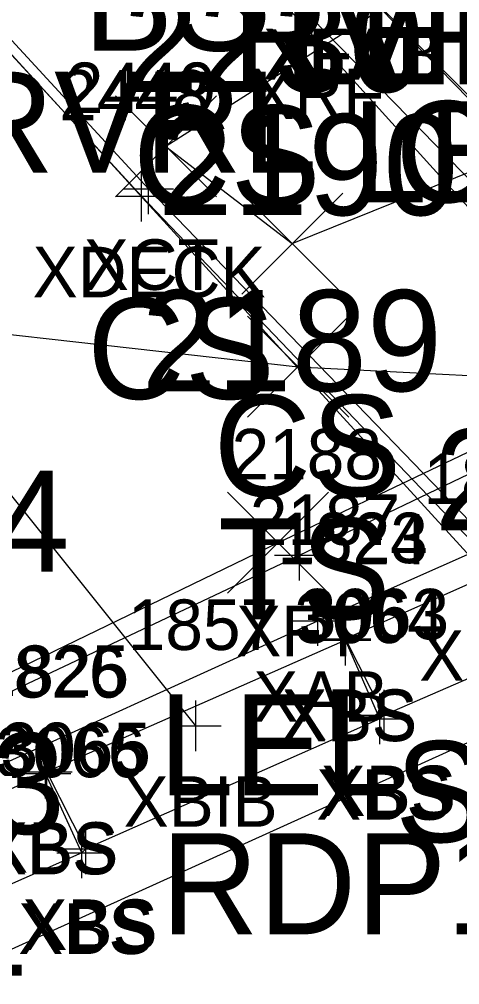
# Model space of a CAD drawing. Extents: x 1504228 to 1506103, y 437717 to 440106.
# Drawn here: x 1505265.52 to 1505274.23, y 438158.68 to 438177.79 of the extents above; entities that cross this region are included whole.
import ezdxf

# ---------------------------------------------------------------- set-up
doc = ezdxf.new("R2010")
doc.units = 0
for name, color, linetype in [('B_A', 7, 'Continuous'), ('B_I', 7, 'Continuous'), ('B_TIC', 7, 'Continuous'), ('BB', 7, 'Continuous'), ('BDC', 7, 'Continuous'), ('BELB', 7, 'Continuous'), ('BF', 7, 'Continuous'), ('BFT', 7, 'Continuous'), ('BR', 7, 'Continuous'), ('BSE', 7, 'Continuous'), ('BSUBM', 7, 'Continuous'), ('L_A', 7, 'Continuous'), ('L_I', 7, 'Continuous'), ('L_TIC', 7, 'Continuous'), ('LARO', 7, 'Continuous'), ('LELB', 7, 'Continuous'), ('P_I', 7, 'Continuous'), ('PET', 7, 'Continuous'), ('R_A', 7, 'Continuous'), ('R_I', 7, 'Continuous')]:
    doc.layers.add(name, color=color, linetype=linetype)

msp = doc.modelspace()

# ---------------------------------------------------------------- linework, layer by layer
at = {"layer": 'B_TIC'}
for p, q in [((1505268.074, 438174.436), (1505268.15, 438174.436)), ((1505267.942, 438174.29), (1505268.017, 438174.29)), ((1505271.067, 438167.183), (1505271.143, 438167.183)), ((1505271.429, 438165.886), (1505271.504, 438165.886)), ((1505271.974, 438165.5), (1505272.049, 438165.5)), ((1505271.977, 438165.525), (1505272.052, 438165.525)), ((1505272.655, 438163.944), (1505272.731, 438163.944)), ((1505272.741, 438164.016), (1505272.817, 438164.016)), ((1505269.013, 438163.806), (1505269.089, 438163.806)), ((1505266.041, 438162.863), (1505266.116, 438162.863)), ((1505266.064, 438162.896), (1505266.14, 438162.896)), ((1505266.76, 438161.287), (1505266.836, 438161.287)), ((1505266.84, 438161.367), (1505266.916, 438161.367))]:
    msp.add_line(p, q, dxfattribs=at)
for points in [[(1505271.307, 438177.317), (1505271.307, 438178.317)], [(1505267.938, 438173.79), (1505267.938, 438174.79)], [(1505268.071, 438173.936), (1505268.071, 438174.936)], [(1505267.571, 438174.436), (1505268.571, 438174.436)], [(1505267.438, 438174.29), (1505268.438, 438174.29)], [(1505271.064, 438166.683), (1505271.064, 438167.683)], [(1505270.564, 438167.183), (1505271.564, 438167.183)], [(1505271.425, 438165.386), (1505271.425, 438166.386)], [(1505271.97, 438165), (1505271.97, 438166)], [(1505271.973, 438165.025), (1505271.973, 438166.025)], [(1505270.925, 438165.886), (1505271.925, 438165.886)], [(1505271.47, 438165.5), (1505272.47, 438165.5)], [(1505271.473, 438165.525), (1505272.473, 438165.525)], [(1505272.738, 438163.516), (1505272.738, 438164.516)], [(1505269.01, 438163.306), (1505269.01, 438164.306)], [(1505272.652, 438163.444), (1505272.652, 438164.444)], [(1505272.152, 438163.944), (1505273.152, 438163.944)], [(1505272.238, 438164.016), (1505273.238, 438164.016)], [(1505268.51, 438163.806), (1505269.51, 438163.806)], [(1505266.037, 438162.363), (1505266.037, 438163.363)], [(1505266.061, 438162.396), (1505266.061, 438163.396)], [(1505265.537, 438162.863), (1505266.537, 438162.863)], [(1505265.561, 438162.896), (1505266.561, 438162.896)], [(1505266.757, 438160.787), (1505266.757, 438161.787)], [(1505266.837, 438160.867), (1505266.837, 438161.867)], [(1505266.257, 438161.287), (1505267.257, 438161.287)], [(1505266.337, 438161.367), (1505267.337, 438161.367)]]:
    msp.add_lwpolyline(points, dxfattribs=at)
at = {"layer": 'BB'}
for points in [[(1505279.36, 438168.588), (1505247.631, 438203.673)], [(1505274.859, 438166.697), (1505243.111, 438201.465)], [(1505269.01, 438163.806), (1505239.92, 438200.195)]]:
    msp.add_lwpolyline(points, dxfattribs=at)
at = {"layer": 'BDC'}
msp.add_lwpolyline([(1505211.925, 438243.921), (1505227.096, 438222.88), (1505239.823, 438206.409), (1505253.849, 438189.887), (1505268.071, 438174.436), (1505276.686, 438165.513)], dxfattribs=at)
at = {"layer": 'BELB'}
msp.add_lwpolyline([(1505211.812, 438243.704), (1505226.972, 438222.631), (1505239.63, 438206.209), (1505253.732, 438189.745), (1505267.938, 438174.29), (1505276.516, 438165.316)], dxfattribs=at)
at = {"layer": 'BF'}
for points in [[(1505211.925, 438243.921), (1505216.347, 438245.376), (1505218.618, 438242.78), (1505219.411, 438243.379), (1505231.883, 438226.243), (1505244.785, 438210.059), (1505258.149, 438194.034), (1505272.082, 438178.605), (1505279.641, 438170.867), (1505278.911, 438170.024), (1505281.091, 438167.856), (1505276.686, 438165.513)], [(1505219.325, 438243.288), (1505231.877, 438226.273), (1505244.695, 438209.964), (1505258.118, 438194.019), (1505272.126, 438178.595), (1505280.957, 438169.659)]]:
    msp.add_lwpolyline(points, dxfattribs=at)
at = {"layer": 'BFT'}
msp.add_lwpolyline([(1505211.711, 438138.978), (1505211.593, 438140.8), (1505215.376, 438142.417), (1505230.303, 438149.002), (1505243.278, 438154.766), (1505246.019, 438155.885), (1505263.291, 438163.511), (1505271.064, 438167.183), (1505276.649, 438169.866), (1505288.201, 438174.699), (1505288.73, 438173.49)], dxfattribs=at)
at = {"layer": 'BR'}
msp.add_lwpolyline([(1505218.618, 438242.78), (1505231.125, 438225.649), (1505244.017, 438209.29), (1505257.36, 438193.318), (1505271.307, 438177.817), (1505278.911, 438170.024)], dxfattribs=at)
at = {"layer": 'BSE'}
for points in [[(1505280.986, 438169.409), (1505277.349, 438167.858), (1505277.284, 438167.888), (1505271.973, 438165.525), (1505271.97, 438165.5), (1505266.061, 438162.896), (1505266.037, 438162.863), (1505260.289, 438160.295)], [(1505281.759, 438167.888), (1505278.121, 438166.325), (1505278.032, 438166.318), (1505272.738, 438164.016), (1505272.652, 438163.944), (1505266.837, 438161.367), (1505266.757, 438161.287), (1505261.073, 438158.776)], [(1505272.652, 438163.944), (1505271.97, 438165.5)], [(1505272.738, 438164.016), (1505271.973, 438165.525)], [(1505266.757, 438161.287), (1505266.037, 438162.863)], [(1505266.837, 438161.367), (1505266.061, 438162.896)]]:
    msp.add_lwpolyline(points, dxfattribs=at)
at = {"layer": 'BSUBM'}
msp.add_lwpolyline([(1505214.761, 438127.389), (1505213.65, 438134.809), (1505212.657, 438139.975), (1505231.134, 438147.944), (1505243.637, 438153.412), (1505246.753, 438154.837), (1505263.932, 438162.477), (1505271.425, 438165.886), (1505277.465, 438168.561), (1505287.974, 438173.167), (1505291.052, 438171.05), (1505297.268, 438166.649), (1505302.136, 438162.984), (1505307.468, 438159.403), (1505307.306, 438158.962)], dxfattribs=at)
at = {"layer": 'L_TIC'}
for points in [[(1505267.419, 438174.277), (1505269.419, 438176.277)], [(1505269.419, 438174.277), (1505267.419, 438176.277)], [(1505269.919, 438172.353), (1505271.919, 438174.353)], [(1505271.919, 438172.353), (1505269.919, 438174.353)], [(1505270.035, 438169.915), (1505272.035, 438171.915)], [(1505272.035, 438169.915), (1505270.035, 438171.915)], [(1505269.634, 438166.43), (1505271.634, 438168.43)], [(1505271.634, 438166.43), (1505269.634, 438168.43)]]:
    msp.add_lwpolyline(points, dxfattribs=at)
at = {"layer": 'LARO'}
msp.add_lwpolyline([(1505211.067, 438140.867), (1505215.631, 438142.954), (1505229.653, 438148.999), (1505242.992, 438154.978), (1505245.889, 438156.33), (1505263.257, 438163.856), (1505270.634, 438167.43), (1505277.265, 438170.598), (1505281.289, 438172.305), (1505281.518, 438175.58), (1505285.106, 438180.489), (1505287.419, 438180.921)], dxfattribs=at)
at = {"layer": 'LELB'}
for points in [[(1505215.631, 438142.954), (1505216.782, 438152.684), (1505223.21, 438155.651), (1505231.417, 438162.88), (1505240.87, 438166.496), (1505250.977, 438169.557), (1505260.591, 438172.084), (1505271.035, 438170.915), (1505277.265, 438170.598), (1505281.518, 438175.58), (1505287.828, 438178.641), (1505292.056, 438179.708), (1505296.753, 438181.832), (1505306.221, 438188.545)], [(1505233.297, 438167.151), (1505239.043, 438168.314), (1505249.04, 438172.836), (1505251.629, 438175.015), (1505261.788, 438177.035), (1505269.325, 438179.089), (1505274.516, 438179.171), (1505268.419, 438175.277), (1505270.919, 438173.353), (1505279.4, 438176.776), (1505285.106, 438180.489)]]:
    msp.add_lwpolyline(points, dxfattribs=at)
at = {"layer": 'PET'}
msp.add_lwpolyline([(1505219.541, 438139.332), (1505229.478, 438143.453), (1505236.137, 438147.016), (1505243.065, 438149.521), (1505252.019, 438153.342), (1505263.781, 438158.664), (1505277.038, 438164.677), (1505295.889, 438147.093), (1505311.676, 438134.175), (1505338.301, 438109.134), (1505363.246, 438092.977), (1505381.83, 438081.07), (1505419.293, 438061.963), (1505441.952, 438049.929), (1505474.016, 438032.73)], dxfattribs=at)

# ---------------------------------------------------------------- texts
at = {"layer": 'B_A'}
for s, p in [('XFAT', (1505270.338, 438176.605)), ('XFAB', (1505270.398, 438176.595)), ('XRF', (1505270.067, 438175.817)), ('XCT', (1505266.791, 438172.436)), ('XDECK', (1505265.781, 438172.29)), ('XFT', (1505269.808, 438165.183)), ('XBIB', (1505273.43, 438164.697)), ('XAB', (1505270.146, 438163.886)), ('XBS', (1505270.71, 438163.5)), ('XBS', (1505270.713, 438163.525)), ('XBS', (1505271.392, 438161.944)), ('XBS', (1505271.478, 438162.016)), ('XBIB', (1505267.581, 438161.806)), ('XBS', (1505264.777, 438160.863)), ('XBS', (1505264.801, 438160.896)), ('XBS', (1505265.497, 438159.287)), ('XBS', (1505265.577, 438159.367))]:
    msp.add_text(s, height=1, dxfattribs=at).set_placement(p)
at = {"layer": 'B_I'}
for s, p in [('2449', (1505266.437, 438175.936)), ('2448', (1505266.308, 438175.79)), ('2188', (1505269.717, 438168.683)), ('1855', (1505273.512, 438168.197)), ('2187', (1505270.079, 438167.386)), ('1824', (1505270.624, 438167)), ('1823', (1505270.627, 438167.025)), ('3064', (1505270.959, 438165.444)), ('3063', (1505271.045, 438165.516)), ('1857', (1505267.663, 438165.306)), ('1826', (1505264.663, 438164.363)), ('1825', (1505264.714, 438164.396)), ('3066', (1505265.037, 438162.787)), ('3065', (1505265.144, 438162.867))]:
    msp.add_text(s, height=1, dxfattribs=at).set_placement(p)
at = {"layer": 'L_A'}
for s, p in [('BS', (1505266.78, 438177.172)), ('RVRL', (1505269.726, 438176.503)), ('LER', (1505270.741, 438176.503)), ('RVRL', (1505264.275, 438174.756)), ('CS', (1505267.766, 438174.089)), ('LER', (1505272.099, 438174.171)), ('CS', (1505272.957, 438174.171)), ('CS', (1505266.86, 438170.277)), ('CS', (1505269.36, 438168.353)), ('TS', (1505269.445, 438165.915)), ('LEL', (1505268.272, 438162.43)), ('LEL', (1505260.895, 438158.856))]:
    msp.add_text(s, height=2, dxfattribs=at).set_placement(p)
at = {"layer": 'L_I'}
for s, p in [('2230', (1505267.573, 438176.353)), ('2190', (1505268.256, 438173.915)), ('2189', (1505267.933, 438170.43)), ('2184', (1505260.564, 438166.856)), ('2184', (1505260.564, 438166.856))]:
    msp.add_text(s, height=2, dxfattribs=at).set_placement(p)
at = {"layer": 'P_I'}
for s, p in [('2564', (1505273.731, 438167.677)), ('2563', (1505260.474, 438161.664)), ('2563', (1505260.474, 438161.664))]:
    msp.add_text(s, height=2, dxfattribs=at).set_placement(p)
at = {"layer": 'R_A'}
for s, p in [('SWP1 BS1 ST', (1505272.952, 438161.502)), ('RDP1 SWP1 ST', (1505268.321, 438159.677))]:
    msp.add_text(s, height=2, dxfattribs=at).set_placement(p)
at = {"layer": 'R_I'}
msp.add_text('2564', height=2, dxfattribs=at).set_placement((1505273.731, 438167.677))

doc.saveas('drawing.dxf')
